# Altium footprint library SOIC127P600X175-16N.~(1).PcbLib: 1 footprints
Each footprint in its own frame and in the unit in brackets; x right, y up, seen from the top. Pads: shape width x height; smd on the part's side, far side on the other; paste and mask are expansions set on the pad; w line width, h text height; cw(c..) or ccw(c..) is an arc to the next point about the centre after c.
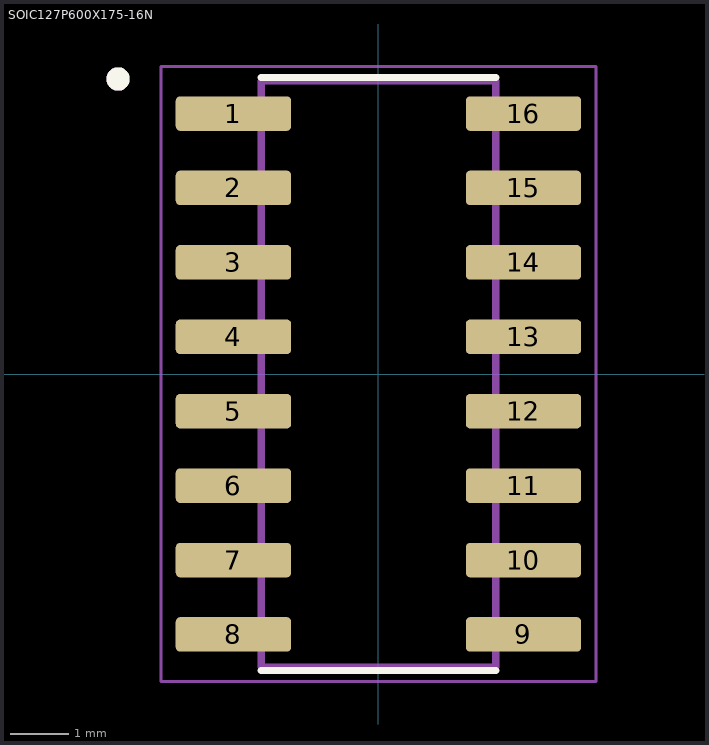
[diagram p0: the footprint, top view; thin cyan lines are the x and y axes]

## SOIC127P600X175-16N [mm]
pads (16):
  rrect25% 1.97x0.59 smd: 1(-2.475,4.445) 2(-2.475,3.175) 3(-2.475,1.905) 4(-2.475,0.635) 5(-2.475,-0.635) 6(-2.475,-1.905) 7(-2.475,-3.175) 8(-2.475,-4.445) 9(2.475,-4.445) 10(2.475,-3.175) 11(2.475,-1.905) 12(2.475,-0.635) 13(2.475,0.635) 14(2.475,1.905) 15(2.475,3.175) 16(2.475,4.445)
Top Overlay:
  circle w0.2: c-4.445,5.035 r0.1
  lines w0.127: -2,-5.06 2,-5.06 ; -2,5.06 2,5.06
Assembly Top:
  circle w0.2: c-4.445,5.035 r0.1
  lines w0.127: -2,-5 -2,5 2,5 2,-5 -2,-5
Courtyard Top:
  lines w0.05: -3.71,-5.25 -3.71,5.25 3.71,5.25 3.71,-5.25 -3.71,-5.25
3D body "step_temp.STEP": height 1.75, standoff 0, extent -3,-4.95 3,4.95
